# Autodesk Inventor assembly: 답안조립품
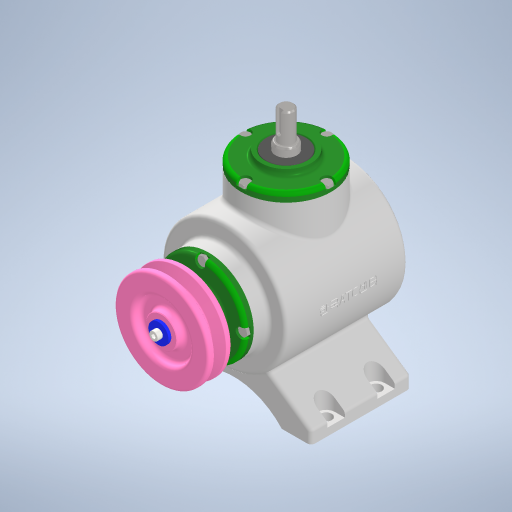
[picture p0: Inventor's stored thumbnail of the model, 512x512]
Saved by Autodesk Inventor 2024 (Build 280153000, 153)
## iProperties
Created: 2023-08
Part Number: 답안조립품
Document SubType Name: Assembly
Designer: Owner
Author: Owner
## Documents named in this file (17)
- C:\Users\Owner\Desktop\730813V1005\답안조립품.iam
- C:\Users\Owner\Desktop\730813V1005\본체.ipt
- C:\Users\Owner\Desktop\730813V1005\V-벨트풀리.ipt
- C:\Users\Owner\Desktop\730813V1005\메인 베벨기어.ipt
- C:\Users\Owner\Desktop\730813V1005\메인 축.ipt
- 메인 축.ipt
- C:\Users\Owner\Desktop\730813V1005\베어링 6203.ipt
- C:\Users\Owner\Desktop\730813V1005\볼트 M4 x 10.ipt
- C:\Users\Owner\Desktop\730813V1005\서브 베벨기어.ipt
- C:\Users\Owner\Desktop\730813V1005\서브 축.ipt
- 서브 축.ipt
- C:\Users\Owner\Desktop\730813V1005\오일실 17 x 32 x 8.ipt
- C:\Users\Owner\Desktop\730813V1005\와셔 4 x 16.ipt
- C:\Users\Owner\Desktop\730813V1005\육각볼트 M4 x 8.ipt
- C:\Users\Owner\Desktop\730813V1005\커버.ipt
- C:\Users\Owner\Desktop\730813V1005\키 4 x 4 x 14.ipt
- C:\Users\Owner\Desktop\730813V1005\키 5 x 5 x 14.ipt
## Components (1 placed, 1 different names)
1. V-벨트풀리:1
